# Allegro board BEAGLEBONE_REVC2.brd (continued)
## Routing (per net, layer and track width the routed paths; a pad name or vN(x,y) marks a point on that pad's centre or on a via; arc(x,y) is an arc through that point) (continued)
DDR_CSN: length 26.9
  TOP w0.121: R63.1 62.17,30.8 v1(63.12,31.75) ; v1(74.73,31.49) 74.33,31.89 U6.L8
  LYR3 w0.133: v1(74.73,31.49) 73.53,31.49 73.41,31.62 73.41,31.88 73.28,32 71.37,32 71.25,32.13 71.25,33.4 71.12,33.53 67.94,33.53 67.82,33.4 67.82,32.26 67.69,32.13 65.53,32.13 65.41,32 65.41,29.46 65.28,29.34 64.77,29.34 64.64,29.21 64.64,27.18 64.52,27.05 64.14,27.05 64.01,27.18 64.01,31.62 63.88,31.75 v1(63.12,31.75)
DDR_D0: length 27.2
  TOP w0.121: U6.G8 74.33,35.09 v1(74.73,35.49)
  LYR3 w0.121: 73.66,35.89 74.33,35.89 v1(74.73,35.49)
  LYR3 w0.133: v1(62.23,36.96) 61.72,37.47 61.72,38.48 64.52,41.27 65.02,41.27 65.91,42.16 67.31,42.16 67.94,41.53 70.1,41.53 72.39,39.24 72.39,34.54 72.64,34.29 73.15,34.29 73.4,34.54 73.4,35.63 73.66,35.89
  BOTTOM w0.121: R44.1 60.13,36.51 60.58,36.96 v1(62.23,36.96)
DDR_D1: length 27.1
  TOP w0.121: U6.G2 v1(69.13,35.49)
  BOTTOM w0.121: R45.1 63.75,37.47 63.88,37.59 63.88,37.97 63.75,38.1 63.37,38.1 63.25,38.23 63.25,38.48 63.37,38.61 63.75,38.61 63.88,38.73 63.88,38.99 63.75,39.12 62.36,39.12 62.23,39.24 62.23,39.63 62.36,39.76 62.65,39.76 62.85,39.76 62.85,39.76 63.5,39.76 63.63,39.88 63.63,41.4 63.75,41.53 64.15,41.53 64.27,41.4 64.27,37.21 64.15,37.08 63.75,37.08 63.63,36.96 63.63,36.7 63.75,36.58 64.01,36.58 64.14,36.45 64.14,36.2 64.01,36.07 63.75,36.07 63.63,35.94 63.63,35.69 63.75,35.56 64.14,35.56 65.41,34.29 68.5,34.29 68.73,34.52 68.73,35.09 v1(69.13,35.49)
DDR_D2: length 27
  TOP w0.121: U6.H7 v1(73.93,34.69) ; v1(62.23,40.77) 61.79,40.32 R46.1
  LYR3 w0.121: v1(73.93,34.69) 74.33,35.09 74.9,35.09 75.86,35.09
  LYR3 w0.133: v1(62.23,40.77) 63.63,42.16 63.63,42.8 64.14,43.31 69.47,43.31 69.98,43.81 73.79,43.81 76.2,41.4 76.2,35.43 75.86,35.09
DDR_D3: length 27.1
  TOP w0.121: U6.H3 v1(69.93,34.69) ; v1(66.04,41.27) R47.1
  LYR3 w0.133: v1(66.04,41.27) 66.45,41.68 67.03,41.68 67.69,41.02 69.9,41.02 71.88,39.04 71.88,34.82 71.75,34.69 71.5,34.69 71.37,34.82 71.37,38.86 71.25,38.99 70.99,38.99 70.87,38.86 70.87,34.82 70.74,34.69 v1(69.93,34.69)
DDR_D4: length 27
  TOP w0.121: U6.H1 v1(68.33,34.69)
  BOTTOM w0.121: R48.1 59.94,38.42 60.07,38.54 60.07,38.75 60.18,38.86 60.34,38.86 60.45,38.75 60.45,37.97 60.58,37.85 60.83,37.85 60.96,37.97 60.96,38.73 61.09,38.86 61.21,38.86 61.34,38.73 61.34,37.97 61.47,37.85 62.61,37.85 62.74,37.97 62.74,38.73 62.61,38.86 62.1,38.86 61.98,38.99 61.98,39.88 62.1,40.01 62.99,40.01 63.12,40.13 63.12,42.67 63.25,42.8 63.5,42.8 63.63,42.67 63.63,41.91 63.75,41.78 65.15,41.78 65.28,41.66 65.28,41.27 65.15,41.15 64.65,41.15 64.52,41.02 64.52,35.55 65.39,34.69 v1(68.33,34.69)
DDR_D5: length 27.1
  TOP w0.121: U6.H9 75.53,34.69 v1(75.53,34.69)
  LYR3 w0.133: v1(75.53,34.69) 76.07,34.69 76.33,34.44 76.33,34.04 76.07,33.78 72.52,33.78 72.14,34.16 72.14,39.12 69.98,41.27 67.82,41.27 67.18,41.92 66.05,41.92 65.15,41.02 64.64,41.02 62.23,38.61 v1(62.23,38.35)
  BOTTOM w0.121: R49.1 61.21,39.37 v1(62.23,38.35)
DDR_D6: length 27.2
  TOP w0.121: U6.F1 v1(68.33,36.29)
  BOTTOM w0.121: R50.1 60.58,40.32 60.71,40.45 60.71,40.89 60.83,41.02 61.59,41.02 61.72,40.89 61.72,40.45 61.85,40.32 62.61,40.32 62.74,40.45 62.74,42.16 62.61,42.29 60.2,42.29 60.07,42.42 60.07,42.93 60.2,43.05 63.75,43.05 63.88,42.93 63.88,42.16 64.01,42.04 65.41,42.04 65.53,41.91 65.53,41.02 65.41,40.89 64.9,40.89 64.77,40.77 64.77,39.88 64.9,39.75 65.41,39.75 65.53,39.62 65.53,39.37 65.41,39.24 64.9,39.24 64.77,39.12 64.77,36.58 65.06,36.29 v1(68.33,36.29)
DDR_D7: length 26.9
  TOP w0.121: v1(75.53,36.29) 75.53,36.29 U6.F9
  LYR3 w0.133: v1(62.23,41.78) 61.59,41.15 61.59,40.49 61.85,40.23 62.33,40.23 64.14,42.04 64.64,42.04 65.66,43.05 69.6,43.05 70.1,43.56 73.66,43.56 75.95,41.27 75.95,36.7 v1(75.53,36.29)
  BOTTOM w0.121: v1(62.23,41.78) 60.58,41.78 60.07,41.27 R51.1
DDR_D8: length 27.2
  TOP w0.121: v1(63.12,35.05) 61.72,33.66 R52.1 ; U6.C8 74.33,38.29 v1(74.73,37.89)
  LYR3 w0.121: 73.15,39.24 73.41,39.24 74.73,37.92 v1(74.73,37.89)
  LYR3 w0.133: 73.15,39.24 70.36,42.04 68.2,42.04 67.56,42.67 65.66,42.67 64.77,41.78 64.26,41.78 60.2,37.72 60.2,35.81 61.37,34.65 62.71,34.65 v1(63.12,35.05)
DDR_D9: length 26.9
  TOP w0.121: v1(62.23,35.05) 61.79,34.61 R53.1 ; U6.C2 v1(69.13,38.69)
  LYR3 w0.121: 68.07,38.29 68.73,38.29 v1(69.13,38.69)
  LYR3 w0.133: v1(62.23,35.05) 61.47,35.05 60.58,35.94 60.58,37.59 60.71,37.72 60.96,37.72 61.09,37.59 61.09,36.2 61.62,35.66 62.61,35.66 62.71,35.76 62.71,36.42 62.84,36.55 63.4,36.55 63.75,36.2 64.74,36.2 64.87,36.32 64.87,37.72 65,37.85 65.66,37.85 65.79,37.72 65.79,34.29 65.91,34.16 66.17,34.16 66.29,34.29 66.29,38.73 66.42,38.86 67.69,38.86 67.82,38.73 67.82,38.42 67.94,38.29 68.07,38.29
DDR_D10: length 27.3
  TOP w0.121: U6.D7 72.79,37.49 72.67,37.62 72.67,40.92 72.77,41.02 74.42,41.02 74.55,41.15 74.55,42.42 74.42,42.55 v1(72.9,42.55) ; v1(71.75,42.55) 71.75,40.89 71.63,40.77 68.04,40.77 67.69,40.42 67.69,36.2 67.4,35.91 63.75,35.91 63.41,35.56 R54.1
  LYR3 w0.133: v1(72.9,42.55) v1(71.75,42.55)
DDR_D11: length 26.9
  TOP w0.121: U6.D3 v1(69.93,37.89)
  LYR3 w0.121: v1(69.93,37.89) 69.53,37.49 67.94,37.49
  LYR3 w0.133: v1(64.01,35.05) 63.75,35.05 62.99,34.29 60.07,34.29 59.94,34.16 59.94,33.66 60.07,33.53 63.47,33.53 63.6,33.66 63.6,34.04 63.73,34.16 64.29,34.16 64.41,34.04 64.41,33.63 64.52,33.53 65.66,33.53 65.79,33.4 65.79,33.02 65.91,32.89 66.93,32.89 67.06,33.02 67.06,34.29 67.18,34.42 67.69,34.42 67.82,34.54 67.82,37.36 67.94,37.49
  BOTTOM w0.121: R55.1 60.13,32.7 62.08,34.65 63.61,34.65 v1(64.01,35.05)
DDR_D12: length 27.3
  TOP w0.121: U6.D1 v1(68.33,37.89)
  LYR3 w0.133: v1(68.33,37.89) 67.69,37.89 67.56,37.76 67.56,34.92 67.44,34.8 67.18,34.8 67.06,34.92 67.06,38.35 66.93,38.48 66.67,38.48 66.55,38.35 66.55,33.27 66.42,33.15 66.17,33.15 66.04,33.27 66.04,33.66 65.91,33.78 64.77,33.78 64.65,33.9 64.65,35.43 64.52,35.56 63.25,35.56 63.12,35.69 v1(63.12,36.07)
  BOTTOM w0.121: v1(63.12,36.07) 63.12,35.69 62.99,35.56 61.85,35.56 61.72,35.43 61.72,34.65 61.62,34.54 61.44,34.54 61.34,34.65 61.34,34.92 61.24,35.03 61.07,35.03 60.96,34.92 60.96,33.88 60.86,33.78 60.68,33.78 60.58,33.88 60.58,34.19 60.48,34.29 60.3,34.29 60.2,34.19 60.2,33.76 60.1,33.66 R56.1
DDR_D13: length 27
  TOP w0.121: v1(74.73,37.09) U6.D9
  LYR3 w0.133: v1(74.73,37.09) 74.22,36.58 73.41,36.58 73.15,36.32 73.15,35.94 73.03,35.81 72.77,35.81 72.64,35.94 72.64,39.37 70.23,41.78 68.07,41.78 67.44,42.42 65.79,42.42 64.9,41.53 64.39,41.53 61.47,38.61 61.47,36.83 v1(62.23,36.07)
  BOTTOM w0.121: v1(62.23,36.07) 61.59,36.07 60.13,34.61 R57.1
DDR_D14: length 26.8
  TOP w0.121: U6.B1 v1(68.33,39.49)
  LYR3 w0.133: v1(68.33,39.49) 67.96,39.12 65.28,39.12 65.15,39.24 65.15,39.75 65.28,39.88 65.79,39.88 66.04,40.13 66.42,40.13 66.67,39.88 67.69,39.88 67.82,40.01 67.82,40.26 67.69,40.39 67.18,40.39 66.8,40.77 64.9,40.77 64.77,40.64 64.77,38.35 64.64,38.23 64.39,38.23 64.26,38.35 64.26,39.62 64.14,39.75 63.88,39.75 63.75,39.62 63.75,37.59 63.63,37.47 63.37,37.47 63.25,37.59 63.25,38.61 63.12,38.73 62.87,38.73 62.74,38.61 62.74,37.97 62.61,37.85 62.36,37.85 62.23,37.72 62.23,37.49 62.36,37.36 62.71,37.36 v1(63.12,36.96)
  BOTTOM w0.121: R58.1 60.07,35.56 60.98,36.47 62.63,36.47 v1(63.12,36.96)
DDR_D15: length 26.9
  TOP w0.121: U6.B9 74.73,39.49 74.73,40.22 v1(74.73,40.29) ; R59.1 61.66,38.42 62.01,38.77 63.88,38.77 64.01,38.64 64.01,38 64.14,37.87 64.64,37.87 64.77,38 64.77,38.99 64.9,39.12 66.17,39.12 66.29,38.99 66.29,36.83 66.42,36.7 66.8,36.7 66.93,36.83 66.93,40.77 67.69,41.53 68.45,41.53 v1(69.47,42.55)
  LYR3 w0.133: v1(74.73,40.29) 74.73,41.83 74.42,42.14 73.79,42.14 73.64,42.29 73.64,43.07 73.41,43.31 70.23,43.31 v1(69.47,42.55)
DDR_DQM0: length 27.1
  TOP w0.121: v1(66.8,41.27) 66.67,41.15 66.67,40.26 66.55,40.13 66.29,40.13 66.17,40.26 66.17,40.64 66.04,40.77 65.82,40.77 65.69,40.64 65.69,39.62 65.57,39.5 64.9,39.5 64.77,39.62 64.77,40.77 64.64,40.89 64.39,40.89 64.26,40.77 64.26,39.24 64.14,39.12 63.88,39.12 63.75,39.24 63.75,40.77 63.63,40.89 63.37,40.89 63.25,40.77 63.25,39.24 63.12,39.12 62.87,39.12 62.74,39.24 62.74,40.13 62.61,40.26 62.36,40.26 62.23,40.13 62.23,39.24 62.1,39.12 61.85,39.12 61.59,39.37 R67.1 ; U6.F3 v1(69.93,36.29)
  LYR3 w0.121: 69.53,40.58 69.53,39.22 69.63,39.12 69.88,39.12 69.98,39.22 69.98,39.78 70.08,39.88 70.38,39.88 70.48,39.78 70.48,36.42 70.36,36.29 v1(69.93,36.29)
  LYR3 w0.133: v1(66.8,41.27) 67.31,40.77 69.34,40.77 69.53,40.58
DDR_DQM1: length 26.9
  TOP w0.121: R70.1 61.72,32.7 63.18,34.16 68.2,34.16 68.47,33.89 70.61,33.89 70.74,34.02 70.74,35.05 70.87,35.18 71.12,35.18 71.25,35.05 71.25,33.66 71.37,33.53 71.63,33.53 71.75,33.66 71.75,38.86 71.63,38.99 71.37,38.99 71.25,38.86 71.25,35.81 71.12,35.69 70.87,35.69 70.74,35.81 70.74,38.68 U6.B3
DDR_DQS0: length 27
  TOP w0.121: R68.1 63.31,42.23 64.9,43.81 74.17,43.81 74.3,43.69 74.3,43.43 74.17,43.31 72.3,43.31 72.17,43.18 72.17,34.92 72.3,34.8 72.77,34.8 72.9,34.92 72.9,35.76 73.03,35.89 U6.F7
DDR_DQS1: length 27.2
  TOP w0.121: v1(70.99,42.55) 71.37,42.16 71.37,41.15 71.25,41.02 67.94,41.02 67.44,40.51 67.44,36.32 67.31,36.2 64.9,36.2 64.77,36.32 64.77,37.25 64.64,37.37 64.39,37.37 64.26,37.25 64.26,36.32 64.14,36.2 63.75,36.2 63.63,36.32 63.63,37.25 63.5,37.37 62.77,37.37 62.65,37.25 62.65,36.64 62.52,36.51 R71.1
  TOP w0.305: U6.B7 73.04,39.58 73.04,40.2 v1(73.13,40.29)
  LYR3 w0.133: v1(73.13,40.29) 72.77,40.29 72.64,40.42 72.64,41.94 72.54,42.04 72.24,42.04 72.14,41.94 72.14,41.27 72.01,41.15 71.88,41.15 71.75,41.27 71.75,41.78 71.63,41.91 71.12,41.91 70.99,42.04 v1(70.99,42.55)
DDR_DQSN0: length 27.2
  TOP w0.121: U6.E8 73.93,36.29 72.52,36.29 72.42,36.4 72.42,41.27 72.55,41.4 73.28,41.4 73.41,41.53 73.41,41.91 73.28,42.04 72.55,42.04 72.42,42.16 72.42,42.95 72.52,43.05 74.42,43.05 74.55,43.18 74.55,43.94 74.42,44.07 64.64,44.07 63.75,43.18 R69.1
DDR_DQSN1: length 27
  TOP w0.121: v1(70.23,42.55) 70.23,41.4 70.1,41.27 69.98,41.27 69.85,41.4 69.85,41.91 69.72,42.04 69.6,42.04 69.47,41.91 69.47,41.4 69.34,41.27 67.82,41.27 67.18,40.64 67.18,36.58 67.06,36.45 66.17,36.45 66.04,36.58 66.04,37.72 65.91,37.85 65.25,37.85 65.02,37.62 61.88,37.62 61.72,37.47 R72.1
  TOP w0.305: U6.A8 v1(73.93,40.29)
  LYR3 w0.133: v1(73.93,40.29) 74.17,40.52 74.17,40.77 74.04,40.89 73.15,40.89 73.03,41.02 73.03,41.27 73.15,41.4 74.17,41.4 74.3,41.53 74.3,41.78 74.17,41.91 73.53,41.91 73.41,42.04 73.41,42.8 73.15,43.05 70.36,43.05 70.23,42.93 v1(70.23,42.55)
DDR_ODT: length 27.2
  TOP w0.121: v1(62.23,29.84) R73.1 ; U6.K9 v1(75.53,32.29)
  LYR3 w0.121: 73.66,32.69 74.12,32.69 74.33,32.47 74.33,32.12 74.57,31.89 75.13,31.89 v1(75.53,32.29)
  LYR3 w0.133: v1(62.23,29.84) 61.72,29.84 61.59,29.72 61.59,28.96 61.47,28.83 60.45,28.83 60.33,28.96 60.33,33.02 60.45,33.15 64.39,33.15 64.52,33.02 64.52,32.77 64.64,32.64 67.18,32.64 67.31,32.77 67.31,33.91 67.44,34.04 71.5,34.04 71.75,33.78 71.75,32.89 71.96,32.69 73.66,32.69
DDR_RASN: length 27.3
  TOP w0.121: U6.K7 73.93,32.29 v1(73.93,32.29)
  LYR3 w0.133: v1(63.12,29.84) 63.12,30.23 62.87,30.48 61.72,30.48 61.59,30.61 61.59,32.13 61.72,32.26 64.26,32.26 64.39,32.13 64.39,30.23 64.52,30.1 64.77,30.1 64.9,30.23 64.9,32.26 65.02,32.38 67.44,32.38 67.56,32.51 67.56,33.66 67.69,33.78 71.37,33.78 71.5,33.66 71.5,32.42 71.63,32.29 v1(73.93,32.29)
  BOTTOM w0.121: R65.1 60.2,29.84 60.71,29.34 62.61,29.34 v1(63.12,29.84)
DDR_RESETN: length 3.5
  TOP w0.121: TP3.1 58.23,30.8 57.14,31.89 55.93,31.89 U5.G2
DDR_VREF: length 21
  TOP w0.121: v1(54.33,33.49) U5.J4 ; U6.J2 v1(69.13,33.09)
  BOTTOM w0.121: v1(54.33,33.49) 54.73,33.09 55.44,33.09 55.63,33.27 57.02,33.27 58.04,32.26 60.33,32.26 60.77,32.7 R74.2 R75.1 62.04,34.04 62.17,34.16 64.77,34.16 65.15,33.78 68.44,33.78 v1(69.13,33.09) 67.93,31.89 C118.1
DDR_VTP: length 18.8
  TOP w0.305: v1(55.13,33.49) U5.J3
  LYR4 w0.381: v1(64.77,20.32) 59.05,26.04 59.05,30.1 55.66,33.49 v1(55.13,33.49)
  BOTTOM w0.381: R76.2 v1(64.77,20.32)
DDR_WEN: length 26.9
  TOP w0.121: R66.1 56.83,22.16 57.15,21.84 61.59,21.84 63.79,24.04 66.26,24.04 67.09,23.21 67.78,23.21 v1(68.2,23.62) ; U6.K3 v1(69.93,32.29)
  LYR3 w0.133: v1(69.93,32.29) 70.47,31.75 72.01,31.75 72.77,30.99 72.77,29.08 71.63,27.94 71.25,27.94 69.85,26.54 69.85,25.78 68.83,24.77 68.83,24.26 v1(68.2,23.62)
EHRPWM1A: length 55.8
  TOP w0.121: v1(36.83,44.2) 39.5,44.2 40.64,43.05 40.89,43.05 41.66,42.29 44.58,42.29 45.53,41.34 45.53,40.69 U5.U14
  LYR4 w0.133: v1(36.83,44.2) 36.83,42.04 36.32,41.53 36.32,39.12 36.83,38.61 37.34,38.61 38.61,37.34 38.61,35.56 35.69,32.64 35.69,26.29 36.07,25.91 36.07,21.21 35.43,20.57 35.43,15.88 35.94,15.37 36.45,15.37 37.06,14.76 37.06,6.83 34.92,4.7 P9.14
EHRPWM1B: length 45.2
  TOP w0.121: v1(45.53,39.89) U5.T14
  LYR4 w0.133: P9.16 37.47,5.59 38.54,6.67 38.54,14.67 37.69,15.52 37.69,26.34 37.4,26.63 36.87,26.63 36.7,26.8 36.7,28.83 39.5,31.62 39.5,38.48 39.24,38.73 39.24,39.37 40.26,40.39 45.03,40.39 v1(45.53,39.89)
EHRPWM2A: length 29.6
  TOP w0.121: U5.U10 49.53,40.69 49.53,41.61 49.38,41.77 49.38,41.89 46.62,44.65 46.62,47.9 46.51,48.01 46.33,48.01 46.23,47.9 46.23,44.81 46.13,44.7 45.95,44.7 45.85,44.81 45.85,47.9 45.75,48.01 45.57,48.01 45.47,47.9 45.47,44.81 45.36,44.7 45.19,44.7 45.09,44.81 45.09,48.32 44.83,48.58 44.13,48.58 43.69,49.02 43.69,51.05 43.43,51.31 42.8,51.31 42.55,51.05 P8.19
EHRPWM2B: length 28.6
  TOP w0.121: v1(48.73,39.89) U5.T10
  LYR4 w0.133: v1(48.73,39.89) 48.15,40.47 47.8,40.47 44.32,43.94 40.39,43.94 40.13,44.2 40.13,48.01 39.88,48.26 39.5,48.26 39.24,48.01 39.24,47.37 38.99,47.12 38.61,47.12 38.35,47.37 38.35,48.01 38.1,48.26 37.72,48.26 37.47,48.01 37.47,45.47 37.21,45.21 36.45,45.21 36.2,45.47 36.2,48.9 P8.13
EMU2R: length 2.8
  BOTTOM w0.121: R183.2 P7.17
EMU3R: length 4.9
  BOTTOM w0.121: P7.18 68.07,17.14 67.82,17.4 R184.1
EMU4R: length 2.8
  BOTTOM w0.121: R185.2 P7.19
EMU_RSTN: length 4.9
  BOTTOM w0.121: C156.1 60.45,15.11 60.58,15.24 61.21,15.24 61.47,15.49 R182.2 P7.15
ENZ_KALDO_1P8V: length 5.2
  TOP w0.121: U5.B4 53.94,28.29 54.33,27.9 54.33,25.7 54.07,25.44 54.07,24.73 54.1,24.7 54.1,24.64 54.93,23.81 R79.2
F_ADBUS0: length 2.6
  TOP w0.121: U12.16 48.84,6.62 48.56,6.35 v1(48.26,6.35)
  BOTTOM w0.121: v1(48.26,6.35) R164.1
F_ADBUS1: length 5.4
  TOP w0.121: v1(52.7,6.99) 51.82,7.87 51.82,9.4 51.63,9.58 U12.17
  BOTTOM w0.121: v1(52.7,6.99) R165.1
F_ADBUS2: length 4.7
  TOP w0.121: v1(52.7,8.26) 52.07,8.89 52.07,9.78 51.76,10.09 U12.18
  BOTTOM w0.121: R166.1 v1(52.7,8.26)
F_ADBUS3: length 3.9
  TOP w0.121: v1(52.7,9.53) 51.65,10.58 U12.19
  BOTTOM w0.121: v1(52.7,9.53) R168.1
F_ADBUS4: length 3.7
  TOP w0.121: v1(52.7,10.79) 51.92,11.58 U12.21
  BOTTOM w0.121: v1(52.7,10.79) R169.1
F_ADBUS6: length 3.6
  TOP w0.121: U12.23 52.19,12.58 v1(52.7,12.06)
  BOTTOM w0.121: v1(52.7,12.06) R170.1
F_ADBUS7: length 5.9
  TOP w0.121: v1(52.7,13.34) 52.7,13.72 52.83,13.84 52.83,15.24 51.99,16.09 U12.30
  BOTTOM w0.121: v1(52.7,13.34) R171.1
F_EECS: length 5.1
  TOP w0.121: R173.2 v1(36.51,9.84) 36.76,10.09 U12.63
  BOTTOM w0.121: v1(36.51,9.84) U13.5
F_EEDATA: length 7.9
  TOP w0.121: R188.2 36.19,11.75 v1(36.2,11.74) 36.85,11.09 U12.61
  BOTTOM w0.121: v1(36.2,11.74) 36.2,11.74 34.85,11.74 33.91,10.79 U13.3
F_EEDOUT: length 11.7
  TOP w0.121: R187.2 33.9,8.89 33.66,8.64 33.66,7.37 v1(33.15,6.86) ; R188.1 v1(33.66,11.75)
  LYR4 w0.133: v1(33.66,11.75) 32.64,10.73 32.64,7.37 v1(33.15,6.86)
  BOTTOM w0.121: v1(33.15,6.86) 33.66,7.37 33.66,8.38 33.15,8.89 U13.1
F_EESK: length 5.1
  TOP w0.121: R174.2 v1(36.51,10.79) 36.72,10.58 U12.62
  BOTTOM w0.121: v1(36.51,10.79) U13.4
FT_DM: length 53.6
  TOP w0.114: U11.28 18.55,39.4 18.26,39.1 18.26,38.24 20.18,36.32 22.49,36.32 23.99,37.82 32.54,37.82 34.29,36.07 34.29,35.42 35.28,34.43 35.28,30.11 35.81,29.58 35.81,22.59 36.97,21.44 38.89,21.44 39.81,20.51 39.81,18.59 42.14,16.27 42.14,15.51 44.56,13.09 44.56,8.94 44.33,8.72
  TOP w0.121: 44.33,8.72 U12.7
FT_DP: length 53.7
  TOP w0.114: 44.84,8.72 44.84,13.2 42.42,15.62 42.42,16.38 40.09,18.71 40.09,20.63 39,21.72 37.08,21.72 36.09,22.71 36.09,29.69 35.56,30.23 35.56,34.54 34.57,35.53 34.57,36.18 32.65,38.1 23.88,38.1 22.38,36.6 20.29,36.6 18.54,38.35 18.54,38.99 18.67,39.12 18.89,39.12 19.14,38.87 U11.1
  TOP w0.121: 44.84,8.72 U12.8
FT_REF: length 2.3
  TOP w0.121: U12.6 43.84,6.65 v1(44.13,6.35)
  BOTTOM w0.121: R167.2 v1(44.13,6.35)
FT_RESETN: length 2.8
  TOP w0.121: U12.14 v1(47.84,9.53)
  BOTTOM w0.121: v1(47.84,9.53) 48.04,9.53 48.26,9.75 48.26,10.29
FT_SRESET: length 37.8
  TOP w0.121: U12.26 v1(52.32,14.09) ; v1(33.97,24.77) 33.97,25.29 U14.5
  LYR3 w0.133: v1(52.32,14.09) 48.38,14.09 47.62,13.34 42.93,13.34 42.16,14.1 40.26,14.1 38.61,12.45 33.72,12.45 v1(33.02,11.75)
  LYR4 w0.133: v1(33.02,11.75) 33.02,12.05 33.03,12.06 33.03,16.9 33.53,17.4 33.53,24.32 v1(33.97,24.77)
  BOTTOM w0.121: v1(33.97,24.77) R162.2
FT_SRESETB: length 1.9
  TOP w0.121: U16.6 34.12,42.97 33.91,43.18 v1(33.53,43.18)
  BOTTOM w0.121: v1(33.53,43.18) R163.1
FT_SRESETN: length 29.8
  TOP w0.121: v1(38.73,20.32) 37.97,21.08 36.7,21.08 35.43,22.35 35.43,24 35.18,24.26 33.53,24.26 33.02,24.77 33.02,25.27 32.51,25.79 U14.3
  LYR3 w0.133: v1(53.21,17.14) 52.7,17.14 50.16,19.68 44.58,19.68 43.43,20.83 40.26,20.83 39.75,20.32 v1(38.73,20.32)
  BOTTOM w0.121: v1(53.21,17.14) 54.1,16.26 R172.1
FT_VBUS: length 48.2
  TOP w0.121: v1(30.86,40.01) 28.45,40.01 27.69,39.24 23.24,39.24 22.87,38.87 U11.7 ; v1(32.38,11.75) 32.83,12.19 33.78,12.19 33.91,12.32 36.83,12.32 R181.2 37.06,12.09 U12.59 ; U14.6 33.24,25.79 v1(33.02,26.01)
  LYR4 w0.133: v1(32.38,11.75) 32.79,12.15 32.79,16.1 32.51,16.38 32.51,25.5 v1(33.02,26.01) 32.99,26.04 31.75,26.04 30.86,26.92 v1(30.86,40.01)
GPIO0_7: length 42.6
  TOP w0.121: v1(45.97,20.32) 45.11,21.18 44.48,21.18 43.69,21.97 R202.1 43.31,22.61 43.18,22.73 43.18,23.5 43.05,23.62 R217.1
  BOTTOM w0.121: P9.42 69.34,5.59 52.45,5.59 51.31,6.73 51.31,11.68 50.8,12.19 48.77,12.19 47.18,13.78 47.18,16.57 45.97,17.78 v1(45.97,20.32)
GPIO0_7SRC: length 13.2
  TOP w0.121: R217.2 42.67,21.84 42.06,21.23 41,21.23 40.13,22.1 40.13,24.38 39.88,24.64 39.88,27.94 40.29,28.36 41.31,28.36 42.04,29.09 U5.C18
GPIO0_26: length 29.2
  TOP w0.121: v1(47.93,39.89) U5.T11
  LYR3 w0.133: v1(47.93,39.89) 43.75,44.07 39.5,44.07 39.24,44.32 39.24,44.83 39.5,45.09 42.49,45.09 42.67,45.27 42.67,45.53 42.49,45.72 v1(36.83,45.72)
  LYR4 w0.133: v1(36.83,45.72) 36.83,49.02 36.07,49.78 36.07,51.56 P8.14
GPIO0_27: length 29.5
  TOP w0.121: P8.17 38.61,48.77 37.72,48.77 37.59,48.64 37.59,45.34 37.72,45.21 37.97,45.21 38.1,45.34 38.1,47.88 38.23,48.01 38.48,48.01 38.61,47.88 38.61,45.34 38.73,45.21 38.99,45.21 39.12,45.34 39.12,47.88 39.24,48.01 39.5,48.01 39.62,47.88 39.62,45.18 40.99,43.81 42.55,43.81 42.8,43.56 44.96,43.56 47.13,41.39 47.13,40.69 U5.U12
GPIO1_0: length 11.7
  TOP w0.121: U5.U7 51.93,40.69 51.93,41.44 49.05,44.32 49.05,49.05 P8.25
GPIO1_1: length 14.1
  TOP w0.121: U5.V7 51.53,41.49 47.88,45.14 47.88,48.51 48.9,49.53 48.9,51.44 P8.24
GPIO1_2: length 32
  TOP w0.121: v1(51.13,39.09) U5.R8
  LYR3 w0.121: v1(51.13,39.09) 50.73,39.49 50.73,40.33
  LYR3 w0.133: 50.73,40.33 44.32,46.74 31.75,46.74 30.23,48.26 26.67,48.26 P8.5
GPIO1_3: length 33.5
  TOP w0.121: v1(51.13,39.89) U5.T8
  LYR3 w0.133: P8.6 26.04,51.44 26.04,49.78 27.3,48.51 30.48,48.51 32,46.99 44.45,46.99 51.13,40.31 v1(51.13,39.89)
GPIO1_4: length 11.5
  TOP w0.121: U5.U8 51.13,40.69 51.13,41.54 47.62,45.05 P8.23
GPIO1_5: length 14
  TOP w0.121: P8.22 46.35,51.44 46.35,49.53 47.37,48.51 47.37,44.95 50.27,42.05 50.73,41.59 U5.V8
GPIO1_6: length 33.8
  TOP w0.121: v1(50.33,39.09) U5.R9
  LYR3 w0.133: P8.3 26.16,46.23 42.67,46.23 46.61,42.29 48.01,42.29 49.91,40.39 49.91,39.51 v1(50.33,39.09)
GPIO1_7: length 35.4
  TOP w0.121: v1(50.33,39.89) U5.T9
  LYR3 w0.133: v1(50.33,39.89) 50.33,40.35 44.2,46.48 26.42,46.48 23.5,49.4 23.5,51.44 P8.4
GPIO1_12: length 28.9
  TOP w0.121: v1(47.13,39.89) U5.T12
  LYR4 w0.133: v1(47.13,39.89) 47.13,40.25 43.94,43.43 39.11,43.43 38.86,43.68 38.86,46.23 38.61,46.48 38.23,46.48 37.97,46.23 37.97,44.96 37.72,44.7 34.67,44.7 31.11,48.26 31.11,51.44 P8.12
GPIO1_13: length 28.8
  TOP w0.121: v1(47.13,39.09) U5.R12
  LYR3 w0.121: 46.73,40.27 46.73,39.49 v1(47.13,39.09)
  LYR3 w0.133: 46.73,40.27 44.83,42.16 41.66,42.16 40.89,41.4 40.13,41.4 39.37,42.16 37.14,42.16 36.96,42.35 36.96,42.61 37.14,42.8 39.62,42.8 39.88,43.05 39.88,43.31 39.62,43.56 36.07,43.56 35.69,43.94 v1(35.69,45.72)
  LYR4 w0.133: P8.11 35.69,46.86 v1(35.69,45.72)
GPIO1_14: length 29.5
  TOP w0.121: U5.V13 46.73,41.41 44.83,43.31 42.67,43.31 42.42,43.56 40.89,43.56 39.6,44.86 37.37,44.86 37.25,44.99 37.25,48.54 37.14,48.64 36.8,48.64 36.7,48.54 36.7,47.35 36.6,47.24 36.42,47.24 36.32,47.35 36.32,48.54 36.22,48.64 36.04,48.64 35.94,48.54 35.94,47.35 35.84,47.24 35.53,47.24 35.43,47.35 35.43,49.05 35.53,49.15 38.35,49.15 38.73,49.53 38.73,51.44 P8.16
GPIO1_15: length 29.6
  TOP w0.121: P8.15 36.07,51.56 31.5,51.56 31.24,51.31 31.24,48.76 31.5,48.51 33.79,48.51 36.1,46.19 36.1,44.9 36.39,44.61 39.43,44.61 40.74,43.31 42.29,43.31 42.55,43.05 44.7,43.05 46.33,41.43 46.33,40.69 U5.U13
GPIO1_16: length 50.4
  TOP w0.121: v1(46.33,39.09) U5.R13
  LYR4 w0.121: v1(46.33,39.09) 46.33,39.27 45.93,39.67 45.93,40.09
  LYR4 w0.133: 45.93,40.09 45.93,40.18 45.47,40.64 40.01,40.64 38.86,39.5 38.86,38.61 39.12,38.35 39.12,33.78 38.54,33.21 38.54,31.18 36.45,29.08 36.45,26.54 36.7,26.29 36.7,16 38.23,14.48 38.23,6.99 36.32,5.08 36.32,3.05 P9.15
GPIO1_17: length 58.2
  TOP w0.121: U5.V14 45.93,41.45 44.58,42.8 v1(41.91,42.8)
  LYR4 w0.121: 43.43,39.49 45.73,39.49 45.93,39.29 45.93,38.93 46.16,38.69 46.5,38.69 46.73,38.92 46.73,39.61 46.73,40.14 46.48,40.39
  LYR4 w0.133: v1(41.91,42.8) 44.07,42.8 46.48,40.39 ; P9.23 46.23,3.3 46.23,5.08 45.47,5.84 45.47,7.49 44.58,8.38 44.58,18.41 43.94,19.05 43.94,20.32 42.67,21.59 42.67,21.95 42.37,22.25 41.12,22.25 40.89,22.48 40.89,23.24 41.78,24.13 41.78,27.56 41.91,27.69 41.91,37.08 42.67,37.85 42.67,38.73 43.43,39.49
GPIO1_28: length 50.9
  TOP w0.121: U5.U18 42.58,40.14 40.24,40.14 40.01,39.91 36.17,39.91 35.31,40.77 32.51,40.77 v1(31.75,40.01)
  LYR4 w0.133: P9.12 33.66,5.71 33.66,10.79 34.42,11.56 34.42,20.7 34.04,21.08 34.04,23.11 34.42,23.5 34.42,25.65 33.53,26.54 32.13,26.54 31.24,27.43 31.24,39.5 v1(31.75,40.01)
GPIO1_29: length 13.7
  TOP w0.121: U5.V6 52.33,41.39 50.01,43.72 50.01,48.1 51.44,49.53 51.44,51.44 P8.26
GPIO1_30: length 12.2
  TOP w0.121: U5.U9 50.33,40.69 50.33,41.64 50.03,41.94 50.03,41.95 47.12,44.85 47.12,48.13 P8.21
GPIO1_31: length 15.6
  TOP w0.121: U5.V9 49.93,41.69 49.78,41.84 46.86,44.76 46.86,48.01 45.85,49.02 44.32,49.02 44.07,49.28 44.07,51.18 P8.20
GPIO2_1: length 17.9
  TOP w0.121: U5.V12 47.53,41.37 45.09,43.81 42.93,43.81 42.67,44.07 41.15,44.07 40.01,45.21 40.01,48.39 41.27,49.66 41.27,51.44 P8.18
GPIO2_6: length 29.2
  TOP w0.121: U5.R1 56.79,38.69 58.1,40.01 58.1,42.35 60.07,44.32 63.06,44.32 v1(63.82,45.09) 63.82,45.85
  LYR4 w0.133: v1(63.82,45.09) 63.82,44.13 64.14,43.81 67.82,43.81 72.26,48.26 74.8,48.26 75.56,49.02 P8.45
  BOTTOM w0.121: 63.82,45.85 v1(63.82,45.09)
GPIO2_7: length 29.8
  TOP w0.121: 62.87,45.85 v1(62.87,45.09) 62.36,44.58 59.94,44.58 57.78,42.42 57.78,40.17 56.7,39.09 55.92,39.09 55.53,38.7 U5.R2
  LYR4 w0.133: v1(62.87,45.09) 63.37,45.59 69.22,45.59 72.52,48.9 73.66,48.9 74.3,49.53 74.3,51.44 P8.46
  BOTTOM w0.121: 62.87,45.85 v1(62.87,45.09)
GPIO2_8: length 28.7
  TOP w0.121: v1(55.13,39.09) U5.R3 ; v1(61.91,45.09) 61.91,45.85
  LYR4 w0.133: v1(61.91,45.09) 62.67,45.85 69.09,45.85 71.88,48.64 71.88,50.8 72.39,51.31 72.77,51.31 73.03,51.05 P8.43
  BOTTOM w0.121: v1(55.13,39.09) 55.35,39.09 55.78,39.52 55.78,41.94 57.4,43.56 60.39,43.56 v1(61.91,45.09) 61.91,45.85
GPIO2_9: length 29.1
  TOP w0.121: v1(60.96,45.09) 60.96,45.85 ; v1(54.33,39.09) U5.R4
  LYR4 w0.133: v1(60.96,45.09) 61.98,46.1 68.64,46.1 71.5,48.96 71.5,51.18 P8.44
  BOTTOM w0.121: 60.96,45.85 v1(60.96,45.09) 59.69,43.81 57.28,43.81 55.53,42.07 55.53,39.73 55.3,39.49 54.73,39.49 v1(54.33,39.09)
GPIO2_10: length 29.4
  TOP w0.121: 60.01,45.85 v1(60.01,45.09) 57.47,42.55 57.47,40.29 56.67,39.49 U5.T1
  LYR3 w0.133: P8.41 71.25,49.4 71.25,49.02 71.12,48.9 70.71,48.9 70.61,48.79 70.61,48.62 70.71,48.51 71.14,48.51 71.25,48.4 71.25,48.24 71.14,48.13 70.71,48.13 70.61,48.03 70.61,47.22 70.51,47.12 69.34,47.12 69.22,46.99 69.22,46.74 69.34,46.61 70.48,46.61 70.61,46.48 70.61,46.23 70.48,46.1 69.09,46.1 68.96,45.97 68.96,44.7 68.83,44.58 60.52,44.58 v1(60.01,45.09)
  BOTTOM w0.121: 60.01,45.85 v1(60.01,45.09)
GPIO2_11: length 29.3
  TOP w0.121: U5.T2 55.93,39.89 56.53,39.89 57.15,40.51 57.15,43.18 v1(59.05,45.09) 59.05,45.85
  LYR3 w0.133: P8.42 71.63,51.56 71.63,46.74 69.22,44.32 59.82,44.32 v1(59.05,45.09)
  BOTTOM w0.121: 59.05,45.85 v1(59.05,45.09)
GPIO2_12: length 29.5
  TOP w0.121: 58.1,45.85 v1(58.1,45.09) ; v1(55.13,39.89) U5.T3
  LYR3 w0.133: P8.39 69.09,49.02 69.98,49.02 70.1,48.9 70.1,48.64 69.98,48.51 69.22,48.51 69.09,48.39 69.09,48.23 69.19,48.13 70,48.13 70.1,48.03 70.1,47.73 70,47.62 68.81,47.62 68.71,47.52 68.71,44.96 68.58,44.83 65.66,44.83 64.77,45.72 58.74,45.72 v1(58.1,45.09)
  BOTTOM w0.121: v1(55.13,39.89) 55.13,40.31 55.13,42.05 58.1,45.02 v1(58.1,45.09) 58.1,45.85
GPIO2_13: length 29.8
  TOP w0.121: v1(54.33,39.89) U5.T4 ; 57.15,45.85 v1(57.15,45.09)
  LYR3 w0.133: v1(57.15,45.09) 58.04,45.97 64.9,45.97 65.79,45.09 68.2,45.09 68.45,45.34 68.45,48.77 68.2,49.02 67.06,49.02 66.8,49.28 66.8,51.56 P8.40
  BOTTOM w0.121: v1(54.33,39.89) 54.86,40.42 54.86,42.8 v1(57.15,45.09) 57.15,45.85
GPIO2_22: length 29.6
  TOP w0.121: v1(52.39,44.01) 52.31,43.93 52.31,42.94 53.53,41.72 53.53,40.69 U5.U5
  LYR4 w0.133: P8.27 52.83,50.04 52.83,45.97 52.96,45.85 53.72,45.85 53.85,45.72 53.85,41.78 53.98,41.66 54.61,41.66 54.74,41.78 54.74,44.45 54.86,44.58 55.12,44.58 55.24,44.45 55.24,41.27 55.12,41.15 53.47,41.15 53.34,41.27 53.34,42.29 53.21,42.42 52.83,42.42 52.7,42.29 52.7,41.27 52.58,41.15 52.2,41.15 52.07,41.27 52.07,43.69 v1(52.39,44.01)
GPIO2_23: length 29.6
  TOP w0.121: v1(53.53,39.09) U5.R5
  LYR4 w0.121: v1(53.53,39.09) 53.93,39.49 53.93,40.21
  LYR4 w0.133: 53.93,40.21 54.1,40.39 57.4,40.39 57.53,40.51 57.53,44.07 57.66,44.2 57.91,44.2 58.04,44.07 58.04,40.51 58.17,40.39 58.42,40.39 58.55,40.51 58.55,48.64 58.42,48.77 57.78,48.77 57.66,48.64 57.66,46.99 57.53,46.86 56.77,46.86 56.64,46.99 56.64,48.77 55.24,50.16
GPIO2_24: length 29.4
  TOP w0.121: U5.V5 53.13,41.61 51.94,42.8 51.94,43.51 v1(51.45,44.01)
  LYR4 w0.133: P8.28 51.31,51.31 49.66,51.31 49.02,50.67 49.02,41.27 49.15,41.15 49.4,41.15 49.53,41.27 49.53,44.32 49.66,44.45 49.91,44.45 50.04,44.32 50.04,41.27 50.16,41.15 51.56,41.15 51.69,41.27 51.69,43.77 v1(51.45,44.01)
GPIO2_25: length 28.9
  TOP w0.121: v1(52.73,39.09) U5.R6
  LYR4 w0.121: v1(52.73,39.09) 53.13,39.49 53.13,40.26
  LYR4 w0.133: 53.13,40.26 53.64,40.77 57.02,40.77 57.15,40.89 57.15,44.07 57.02,44.2 56.77,44.2 56.64,44.07 56.64,42.42 56.52,42.29 55.78,42.29 55.65,42.42 55.65,48.64 55.52,48.77 54.86,48.77 54.74,48.64 54.74,46.99 54.61,46.86 53.98,46.86 53.85,46.99 53.85,51.31 55.24,52.7
GPIO3_18: length 11.2
  TOP w0.121: R202.2 44.17,23.14 44.17,21.87 44.61,21.43 45,21.43 45.25,21.67 45.25,25.94 45.9,26.6 46.43,26.6 47.13,27.3 47.13,27.89 U5.B12
GPIO3_19: length 31.2
  TOP w0.121: v1(46.33,28.69) U5.C13
  LYR4 w0.133: v1(46.33,28.69) 45.85,28.21 45.85,26.8 45.47,26.42 45.47,23.37 45.72,23.11 45.72,21.97 48.36,19.33 48.36,7.77 50.16,5.97 50.93,5.97 51.56,5.33 51.56,3.05 P9.27
GPIO3_20: length 5.9
  TOP w0.121: v1(46.33,30.29) U5.D13
  BOTTOM w0.121: v1(46.33,30.29) 45.93,29.89 45.93,28.4 45.59,28.07 R221.2
GPIO3_21: length 30
  TOP w0.121: v1(44.83,22.61) 44.7,22.73 44.7,25.91 45.78,26.98 45.78,27.34 U5.A14
  LYR4 w0.133: v1(44.83,22.61) 44.32,22.1 44.32,21.72 45.21,20.83 45.21,20.32 46.35,19.18 46.35,17.53 47.18,16.7 47.18,12 47.37,11.81 47.37,8.26 50.04,5.59 50.67,5.59 51.18,5.08 51.18,2.92 P9.25
GRN_C: length 2
  BOTTOM w0.121: R128.2 5.21,32.26 4.88,32.59 P10.10
GRNA: length 33.3
  TOP w0.121: v1(25.4,28.96) 25.28,29.07 U15.3
  LYR3 w0.133: P10.9 3.35,30.94 7.62,26.67 9.4,26.67 11.68,24.38 17.53,24.38 19.56,26.42 20.7,26.42 23.75,29.46 24.89,29.46 v1(25.4,28.96)
HS_IND: length 9.3
  TOP w0.121: U11.16 21.95,44.43 22.86,45.34 22.86,47.75 23.28,48.17 24.48,48.17 25.91,46.74 TP8.1
HUB_BIAS: length 3.3
  TOP w0.121: v1(17.14,39.69) 17.14,40.01 17.91,40.77 U11.26
  BOTTOM w0.121: R157.1 16.95,39.05 17.14,39.24 v1(17.14,39.69)
I2C0_SCL: length 37.9
  TOP w0.121: v1(29.72,14.86) 29.07,15.51 U2.28 ; v1(43.93,28.69) U5.C16
  LYR3 w0.133: v1(29.72,14.86) 30.48,14.86 34.42,18.8 40.39,18.8 v1(41.91,20.32)
  BOTTOM w0.121: v1(41.91,20.32) 42.42,19.81 43.19,19.81 43.43,20.06 43.43,21.46 43.18,21.72 43.18,26.92 43.53,27.27 43.53,28.29 v1(43.93,28.69) ; 29.78,9.27 28.45,9.27 28.19,9.53 28.19,11.43 29.32,12.55 29.32,14.46 v1(29.72,14.86) 30.1,15.24 31.5,15.24 31.75,14.99 R7.2
I2C0_SDA: length 32.9
  TOP w0.121: v1(29.72,14.16) 29.34,14.53 29.34,14.67 28.91,15.11 U2.27 ; U5.C17 43.13,28.69 42.15,28.69 41.4,27.94 v1(40.51,27.94)
  LYR3 w0.133: v1(29.72,14.16) 29.31,14.57 29.31,15.09 29.57,15.34 30.58,15.34 34.29,19.05 39.24,19.05 v1(40.51,20.32)
  LYR4 w0.133: v1(40.51,20.32) 40.51,20.83 39.88,21.46 39.88,27.3 v1(40.51,27.94)
  BOTTOM w0.121: R4.2 30.04,14.48 v1(29.72,14.16) 30.12,13.76 30.12,11.64 29.78,11.3 U7.5
I2C1_SCL: length 33.2
  TOP w0.121: U5.A16 v1(43.93,27.09)
  LYR4 w0.133: v1(38.1,17.27) 38.1,18.16 38.23,18.29 38.73,18.29 38.86,18.16 38.86,3.05 P9.17
  BOTTOM w0.121: v1(43.93,27.09) 43.43,26.59 43.43,21.84 43.69,21.59 43.69,19.94 43.31,19.56 40.39,19.56 v1(38.1,17.27)
I2C1_SDA: length 33
  TOP w0.121: U5.B16 v1(43.93,27.89)
  LYR3 w0.133: v1(37.21,27.05) 38.73,28.57 43.24,28.57 v1(43.93,27.89)
  LYR4 w0.133: v1(37.21,27.05) 37.21,27.3 37.34,27.43 37.85,27.43 37.97,27.3 37.97,20.45 39.5,18.92 39.5,6.73 40.01,6.22 P9.18
I2C2_SCL: length 33.8
  TOP w0.121: U5.D17 43.13,29.49 42.06,29.49 41.18,28.6 40.16,28.6 39.5,27.94 39.5,27.56 v1(38.99,27.05)
  LYR4 w0.133: v1(38.99,27.05) 38.48,26.54 38.48,21.72 39.5,20.7 39.5,19.81 40.01,19.3 40.01,10.03 43.56,6.48 43.56,2.92 P9.19
I2C2_SDA: length 33.7
  TOP w0.121: U5.D18 42.08,29.89 41.04,28.85 40.03,28.85 39.12,27.94 v1(38.99,27.94)
  LYR4 w0.133: v1(38.99,27.94) 38.23,27.18 38.23,21.46 39.26,20.43 39.26,19.67 39.75,19.18 39.75,7.24 40.89,6.1 41.15,6.1 41.27,6.22 41.27,7.62 41.4,7.75 41.66,7.75 41.78,7.62 41.78,5.21 P9.20
JTAG_EMU0: length 37
  TOP w0.121: v1(62.29,13.97) 62.17,13.84 R176.2 60.83,13.84 60.38,13.39 60.38,12 59.94,11.56 56.77,11.56 v1(56.26,12.06) ; v1(45.53,28.69) U5.C14
  LYR4 w0.133: v1(47.62,14.61) 48.13,15.11 48.13,19.18 45.47,21.84 45.47,22.86 45.21,23.11 45.21,26.54 45.53,26.86 v1(45.53,28.69)
  BOTTOM w0.121: v1(62.29,13.97) 62.29,14.38 62.52,14.61 P7.13 ; v1(47.62,14.61) 47.62,13.97 49.02,12.57 54.99,12.57 55.12,12.45 R170.2 v1(56.26,12.06)
JTAG_EMU1: length 43
  TOP w0.121: U5.B14 45.53,27.89 45.53,27.11 44.41,26 44.41,22.26 v1(44.83,21.84)
  LYR4 w0.133: v1(44.83,21.84) 45.09,21.84 46.99,19.94 46.99,17.65 47.62,17.02 v1(47.62,16.38)
  BOTTOM w0.121: v1(47.62,16.38) 48.26,15.75 48.26,13.72 49.15,12.83 54.99,12.83 55.12,12.95 R171.2 56.9,13.34 59.44,10.79 R179.2 60.45,11.24 60.64,11.43 66.1,11.43 66.87,12.19 66.87,13.72 67.75,14.61 P7.14
JTAG_TCK: length 40.7
  TOP w0.121: U5.A12 47.53,27.34 46.54,26.35 46.06,26.35 45.5,25.79 45.5,23.58 45.5,21.95 47.26,20.19 47.55,20.19 49.02,20.19 49.21,20.01 49.21,18.02 48.97,17.78 48.39,17.78 47.18,16.57 47.18,11.75 49.18,9.74 49.18,8.85 v1(49.78,8.26)
  LYR3 w0.133: v1(59.63,12.06) 55.31,7.75 50.29,7.75 v1(49.78,8.26)
  BOTTOM w0.121: R164.2 49.66,8.13 v1(49.78,8.26) ; R180.1 R178.1 v1(59.63,12.06)
JTAG_TDI: length 57.4
  TOP w0.121: v1(56.01,6.99) 55.5,6.48 52.32,6.48 49.53,9.27 49.53,9.9 48.13,11.3 48.13,16.89 48.64,17.4 49.08,17.4 49.56,17.87 49.56,17.94 49.56,20.16 49.18,20.54 47.4,20.54 45.85,22.09 45.85,23.72 45.85,24.51 47.08,25.75 47.08,26.39 47.94,27.26 47.94,27.9 U5.B11
  BOTTOM w0.121: 64.29,8.26 66.55,8.26 67.18,7.62 71.25,7.62 71.37,7.49 71.37,6.22 71.12,5.97 57.02,5.97 v1(56.01,6.99) R165.2
JTAG_TDO: length 40.5
  TOP w0.121: v1(52.7,11.43) 53.14,11.86 53.14,16.08 50.04,19.18 50.04,20.19 49.28,20.95 47.5,20.95 46.2,22.25 46.2,24.23 48.24,26.27 48.24,26.97 48.33,27.05 U5.A11
  BOTTOM w0.121: P7.7 63.18,10.79 62.55,10.16 58.17,10.16 56.9,11.43 v1(52.7,11.43) 52.2,10.92 52.2,8.13 52.7,7.62 54.86,7.62 55.12,7.87 R166.2
JTAG_TMS: length 36
  TOP w0.121: v1(47.93,28.69) U5.C11
  LYR4 w0.133: v1(52.7,8.89) 51.82,9.78 51.82,15.49 51.31,16 51.31,18.29 49.05,20.55 49.05,27.57 v1(47.93,28.69)
  BOTTOM w0.121: P7.1 62.61,6.99 61.98,6.35 59.05,6.35 55.88,9.53 R168.2 55.12,9.14 54.86,8.89 v1(52.7,8.89)
JTAG_TRSTN: length 43.3
  TOP w0.121: v1(52.7,10.16) 53.39,10.85 53.39,16.21 50.29,19.3 50.29,20.32 49.4,21.21 47.62,21.21 46.45,22.39 46.45,24.09 48.51,26.16 48.51,26.8 48.73,27.01 48.73,27.89 U5.B10
  BOTTOM w0.121: v1(52.7,10.16) 54.99,10.16 55.12,10.29 R169.2 55.88,10.79 59.05,7.62 61.21,7.62 61.47,7.37 R186.1 62.1,6.99 62.74,7.62 66.55,7.62 67.18,6.99 P7.2
LDO3: length 9.1
  TOP w0.121: v1(20.57,20.32) 21.84,21.59 26.16,21.59 26.54,21.21 26.54,20.73 26.38,20.57 26.38,19.6 U2.40
  BOTTOM w0.121: R19.1 v1(20.57,20.32)
LDO4: length 2.5
  TOP w0.121: v1(25.2,20.95) U2.43
  BOTTOM w0.121: R121.1 25.4,21.15 v1(25.2,20.95)
LDO_PGOOD: length 13.1
  TOP w0.121: U2.46 v1(24,20.32)
  LYR4 w0.133: v1(24,20.32) 24,20.7 23.88,20.83 23.88,23.11 25.02,24.26 29.65,24.26 v1(30.16,24.77)
  BOTTOM w0.121: R141.2 30.77,26.54 30.64,26.42 30.64,24.89 30.51,24.77 v1(30.16,24.77)
LED2: length 28.7
  TOP w0.121: U15.2 24.78,29.1 v1(24.64,28.96)
  LYR3 w0.133: P10.12 4.88,24.43 6.86,26.42 9.27,26.42 11.56,24.13 17.65,24.13 19.68,26.16 20.83,26.16 23.11,28.45 24.13,28.45 v1(24.64,28.96)
  BOTTOM w0.121: R219.1 5.21,25.1 4.88,24.77 P10.12
LEDAA: length 2.5
  TOP w0.121: D2.2 TP10.1 R96.2
LEDAC: length 34.6
  TOP w0.121: v1(33.53,47.75) 33.77,47.51 Q1.6 ; D2.1 2.73,47.75 v1(2.16,47.75)
  BOTTOM w0.121: v1(2.16,47.75) 16.13,47.75 17.4,49.02 32.26,49.02 v1(33.53,47.75)
LEDBA: length 2.5
  TOP w0.121: D3.2 TP11.1 R97.2
LEDBC: length 36.6
  TOP w0.121: Q1.3 32.27,45.2 v1(32.51,44.96) ; D3.1 v1(2.16,46.67)
  BOTTOM w0.121: v1(32.51,44.96) 31.37,44.96 30.86,45.47 30.86,46.1 31.37,46.61 31.37,47.37 29.97,48.77 17.53,48.77 16.26,47.5 2.98,47.5 v1(2.16,46.67)
LEDCA: length 2.5
  TOP w0.121: D4.2 TP12.1 R98.2
LEDCC: length 31.2
  TOP w0.121: Q2.6 29.96,47.51 v1(29.72,47.75) ; D4.1 v1(2.16,45.09)
  BOTTOM w0.121: v1(2.16,45.09) 4.32,47.24 16.38,47.24 17.65,48.51 28.96,48.51 v1(29.72,47.75)
LEDDA: length 2.5
  TOP w0.121: R99.2 TP13.1 D5.2
LEDDC: length 33.3
  TOP w0.121: D5.1 v1(2.16,43.5) ; Q2.3 28.46,45.2 v1(28.7,44.96)
  BOTTOM w0.121: v1(2.16,43.5) 5.65,46.99 16.51,46.99 17.78,48.26 26.8,48.26 27.16,47.9 27.16,45.36 27.56,44.96 v1(28.7,44.96)
MDIO_CLK: length 16.8
  TOP w0.121: v1(36.45,36.83) 36.96,37.34 39.24,37.34 39.62,36.96 41.27,36.96 42.04,36.2 42.63,36.2 U5.M18 ; v1(28.45,35.81) 27.79,35.15 U15.17
  BOTTOM w0.121: v1(36.45,36.83) 36.2,37.08 32.64,37.08 32.13,36.58 29.21,36.58 v1(28.45,35.81)
MDIO_DATA: length 20.1
  TOP w0.121: v1(37.21,36.83) 37.72,36.32 38.48,36.32 38.86,36.7 41.02,36.7 41.83,35.89 43.13,35.89 U5.M17 ; U15.16 28.8,34.14 28.96,34.29 28.96,35.43 v1(29.34,35.81)
  BOTTOM w0.121: v1(37.21,36.83) 36.7,36.32 36.07,36.32 35.56,36.83 32.89,36.83 32.38,36.32 29.84,36.32 v1(29.34,35.81) 28.13,34.61 R131.2
MMC0_CLKO: length 73.4
  TOP w0.121: R192.2 v1(80.52,34.54) ; U5.G17 43.13,32.69 42.34,32.69 41.4,31.75 40.39,31.75 39.62,30.99 38.86,30.99 36.45,28.57 36.45,22.99 v1(37.21,22.23)
  LYR3 w0.133: v1(37.21,22.23) 37.87,21.57 39.35,21.57 41.53,23.75 56.01,23.75 57.4,22.35 71.25,22.35 74.3,25.4 78.11,25.4 81.53,28.83 81.53,33.53 v1(80.52,34.54)
  BOTTOM w0.121: v1(80.52,34.54) R192.2 81.6,34.22 P4.5
MMC0_CMD: length 72.5
  TOP w0.121: v1(37.21,22.99) 36.7,23.5 36.7,28.07 38.35,29.72 39.02,29.72 40.04,30.73 40.77,30.73 42.32,32.29 U5.G18 ; R191.2 v1(80.52,31.75)
  LYR3 w0.133: v1(37.21,22.99) 38.38,21.82 39.22,21.82 41.4,24 59.69,24 59.82,23.88 59.82,23.5 59.69,23.37 57.78,23.37 57.66,23.24 57.66,22.73 57.78,22.61 71.12,22.61 74.17,25.65 77.85,25.65 81.28,29.08 81.28,30.99 v1(80.52,31.75)
  BOTTOM w0.121: P4.3 81.55,32.02 R191.2 v1(80.52,31.75)
MMC0_DAT0: length 72.5
  TOP w0.121: v1(43.93,31.89) U5.G16 ; R193.2 v1(80.52,36.58)
  LYR3 w0.133: v1(80.52,36.58) 80.9,36.58 82.04,35.43 82.04,28.32 78.61,24.89 74.55,24.89 71.5,21.84 56.9,21.84 56.37,22.37 47.87,22.37 47.75,22.48 47.75,22.65 47.87,22.76 50.31,22.76 50.42,22.87 50.42,23.02 50.31,23.13 44.45,23.13 43.9,22.58 41.81,22.58 41.4,22.99 v1(41.4,22.99)
  LYR4 w0.133: v1(43.93,31.89) 43.73,31.89 43.22,31.38 42.55,30.71 42.55,27.62 42.74,27.43 42.74,24.32 v1(41.4,22.99)
  BOTTOM w0.121: v1(80.52,36.58) 82.36,36.58 P4.7
MMC0_DAT1: length 72.2
  TOP w0.121: R194.2 v1(80.52,37.59) ; v1(44.73,31.89) U5.G15
  LYR3 w0.133: v1(80.52,37.59) 80.01,37.08 80.01,36.32 80.26,36.07 80.9,36.07 81.79,35.18 81.79,28.57 78.36,25.15 74.42,25.15 71.37,22.1 57.15,22.1 56.64,22.61 52.44,22.61 52.32,22.72 52.32,22.88 52.44,22.99 54.48,22.99 54.61,23.11 54.61,23.37 54.48,23.5 44.2,23.5 43.69,22.99 v1(42.04,22.99)
  LYR4 w0.121: v1(44.73,31.89) 44.33,31.49 43.76,31.49 43.55,31.27
  LYR4 w0.133: 43.55,31.27 42.8,30.52 42.8,27.86 42.97,27.69 42.97,23.92 v1(42.04,22.99)
  BOTTOM w0.121: P4.8 82.44,37.59 v1(80.52,37.59)
MMC0_DAT2: length 72.3
  TOP w0.121: U5.F18 41.89,31.49 40.88,30.48 40.13,30.48 39.12,29.46 38.73,29.46 37.72,28.45 37.72,23.5 v1(38.99,22.23) ; R190.2 v1(80.52,29.72)
  LYR3 w0.133: v1(38.99,22.23) 38.48,22.73 38.48,23.24 39.75,24.51 52.7,24.51 54.23,26.04 61.59,26.04 61.72,25.91 61.72,25.65 61.59,25.53 58.55,25.53 58.42,25.4 58.42,25.15 58.55,25.02 61.59,25.02 61.72,24.89 61.72,23.24 61.85,23.11 70.87,23.11 73.91,26.16 77.34,26.16 80.52,29.34 v1(80.52,29.72)
  BOTTOM w0.121: v1(80.52,29.72) 82.41,29.72 P4.1
MMC0_DAT3: length 72.4
  TOP w0.121: v1(38.99,22.99) 37.97,24 37.97,28.32 38.86,29.21 39.24,29.21 40.25,30.22 41.01,30.22 41.88,31.09 43.13,31.09 U5.F17 ; R195.2 v1(80.52,30.73)
  LYR3 w0.133: v1(38.99,22.99) 40.26,24.26 52.96,24.26 54.23,25.53 57.78,25.53 57.91,25.4 57.91,25.15 57.78,25.02 54.36,25.02 54.23,24.89 54.23,24.64 54.36,24.51 61.09,24.51 61.21,24.38 61.21,22.99 61.34,22.86 70.99,22.86 74.04,25.91 77.6,25.91 81.03,29.34 81.03,30.23 v1(80.52,30.73)
  BOTTOM w0.121: P4.2 82.33,30.73 v1(80.52,30.73)
Net_69: length 0.6
  TOP w0.121: v1(46.33,39.89) 46.73,39.49
Net_134: length 0.6
  TOP w0.121: 69.53,36.69 v1(69.13,37.09)
Net_135: length 0.6
  TOP w0.121: 69.53,39.89 v1(69.13,40.29)
Net_136: length 0.6
  TOP w0.121: 70.33,28.69 v1(69.93,28.29)
Net_137: length 0.6
  TOP w0.121: 73.53,28.69 v1(73.93,28.29)
Net_271: length 0.6
  TOP w0.121: v1(54.33,32.69) 53.93,33.09
Net_274: length 0.6
  TOP w0.121: v1(45.53,39.09) 45.93,38.69
NINT/RXCLK/PHYAD1: length 3
  BOTTOM w0.121: 21.46,27.62 21.46,28.57 22.16,28.57 v1(23.11,29.53)
NON_REM1: length 3.6
  TOP w0.121: 25.53,41.91 24.38,41.91 24,42.29 23.37,42.29 U11.13 ; 25.53,41.91 R158.1 ; 25.53,41.91 R154.2
NON_REM2: length 6.3
  TOP w0.121: TP7.1 19.68,45.85 20.45,45.08 U11.19
OSC0_IN: length 13.3
  TOP w0.121: 44.45,45.85 43.18,45.85 43.18,45.09 v1(43.69,44.58) 43.95,44.32 46.6,44.32 49.13,41.79 U5.V10
  BOTTOM w0.121: Y2.3 45.3,45.55 Y3.3 43.69,45.51 v1(43.69,44.58)
OSC0_OUT: length 10.6
  TOP w0.121: 41.91,45.85 41.91,45.21 43.05,44.07 46.5,44.07 48.73,41.84 48.73,40.69 U5.U11
OSC0_OUT1: length 7.3
  TOP w0.121: R21.2 R24.1 ; R24.1 C27.1 ; R24.1 41.91,47.62 v1(41.4,48.13)
  BOTTOM w0.121: Y2.1 39.79,47.16 Y3.1 41.4,47.2 v1(41.4,48.13)
OSC1_IN: length 11
  TOP w0.121: Y1.1 55.24,19.59 v1(55.24,20.32) 54.99,20.57 54.36,20.57 52.96,21.97 52.96,25.53 52.67,25.82 52.67,27.15 U5.A6
  BOTTOM w0.121: C23.2 v1(55.24,20.32)
OSC1_OUT: length 4
  TOP w0.121: R22.2 53.85,23.81 53.85,24.6 53.82,24.63 53.82,25.54 54.08,25.8 54.08,26.94 53.93,27.1 U5.A4
OSC1_OUT1: length 7.3
  TOP w0.121: R22.1 53.98,22.23 54.86,21.34 56.2,21.34 56.96,20.57 57.53,20.57 v1(57.78,20.32) 57.78,19.59 Y1.2
  BOTTOM w0.121: C24.2 v1(57.78,20.32)
P_BYPASS: length 3.4
  TOP w0.121: v1(22.73,20.32) 23.37,20.32 23.6,20.09 U2.47
  BOTTOM w0.121: v1(22.73,20.32) 22.73,21.27 C5.2
P_INT_LDO: length 4.4
  TOP w0.121: U2.48 22.71,19.58 22.1,20.19 v1(22.1,20.83)
  BOTTOM w0.121: v1(22.1,20.83) 21.34,20.83 20.19,21.97 C4.2
P_L1: length 1
  TOP w0.203: U2.20 26,12.45
P_L2: length 0.6
  TOP w0.203: 27.2,12.8 U2.23
P_L3: length 1.1
  TOP w0.203: U2.31 29.01,16.71 ; 29.01,16.71 29.26,16.71 ; 29.01,16.71 29.21,16.51
P_MUXIN: length 6.6
  TOP w0.121: v1(23.11,12.45) 23.22,12.45 23.6,12.83 U2.14
  BOTTOM w0.121: R2.1 R1.2 22.48,9.4 22.35,9.53 22.35,11.68 v1(23.11,12.45)
P_MUXOUT: length 12.6
  TOP w0.121: v1(23.88,12.45) 24,12.45 24.4,12.84 U2.16
  LYR4 w0.133: v1(23.88,12.45) 27.69,16.26 v1(27.69,20.95)
  BOTTOM w0.121: v1(27.69,20.95) 27.3,21.34 R8.2
P_WAKEUP: length 3.4
  TOP w0.121: v1(22.35,12.45) 22.35,12.95 22.83,13.44 U2.13
  BOTTOM w0.121: v1(22.35,12.45) 22.83,12.92 23.27,12.92 R11.1
PDDR_A0: length 7.1
  TOP w0.121: U5.F3 v1(55.13,31.09)
  BOTTOM w0.121: v1(55.13,31.09) 55.28,31.24 56.52,31.24 56.75,31.01 56.75,28.83 56.88,28.7 57.57,28.7 57.89,28.38 58.55,28.38 58.67,28.51 58.67,28.77 R29.2
PDDR_A1: length 6.5
  TOP w0.121: R25.2 59.44,31.75 59.04,32.15 58.83,32.15 57.97,32.15 57.66,32.46 57.66,32.56 57.73,32.64 58.6,32.64 58.67,32.71 58.67,32.82 58.6,32.89 57.35,32.89 57.15,33.09 U5.H1
PDDR_A2: length 8
  TOP w0.121: U5.E4 v1(54.33,30.29)
  BOTTOM w0.121: R30.2 57.91,26.04 57.47,26.48 57.47,27.5 57.09,27.88 56.2,27.88 56.01,28.07 56.01,29.46 55.63,29.84 54.78,29.84 v1(54.33,30.29)
PDDR_A3: length 7.2
  TOP w0.121: v1(55.13,28.69) U5.C3
  BOTTOM w0.121: R26.2 56.83,27.1 56.73,27.2 55.6,27.2 55.5,27.3 55.5,27.71 55.4,27.81 55.22,27.81 55.12,27.71 55.12,27.3 55.02,27.2 54.84,27.2 54.74,27.3 54.74,28.09 54.84,28.19 55.03,28.19 55.13,28.3 v1(55.13,28.69)
PDDR_A4: length 7.2
  TOP w0.121: U5.C2 55.93,28.69 56.65,28.69 58.18,27.16 58.18,24.68 58.74,24.13 R31.2
PDDR_A5: length 7.1
  TOP w0.121: U5.B1 56.7,28.29 57.14,27.85 57.14,27.3 57.27,27.18 57.78,27.18 57.91,27.05 57.91,26.8 57.78,26.67 57.26,26.67 57.15,26.56 57.15,26.4 57.26,26.28 57.78,26.28 57.94,26.13 57.94,24.38 57.78,24.23 R32.2
PDDR_A6: length 6.6
  TOP w0.121: v1(53.53,29.49) U5.D5
  BOTTOM w0.121: R33.2 54.99,25.34 54.99,26.43 54.88,26.54 54.72,26.54 54.61,26.43 54.61,26.15 54.5,26.04 54.34,26.04 54.23,26.15 54.23,28.13 53.93,28.43 53.93,28.65 53.93,29.09 v1(53.53,29.49)
PDDR_A7: length 7.4
  TOP w0.121: U5.E2 55.93,30.29 56.58,30.29 59.19,27.68 59.19,26.28 59.44,26.04 R34.2
PDDR_A8: length 8.2
  TOP w0.121: v1(54.33,29.49) U5.D4
  BOTTOM w0.121: R35.2 58.1,25.08 57.15,26.04 57.15,27.43 57.02,27.56 56.01,27.56 55.75,27.81 55.75,29.08 55.35,29.49 v1(54.33,29.49)
PDDR_A9: length 8
  TOP w0.121: U5.C1 56.63,29.09 58.43,27.29 58.43,27.06 58.43,27.06 58.43,25.01 59.37,24.07 59.37,23.37 59.56,23.18 R36.2
PDDR_A10: length 7.1
  TOP w0.121: U5.F4 v1(54.33,31.09)
  BOTTOM w0.121: R37.2 58.42,27.81 57.91,27.81 57.35,28.37 56.72,28.37 56.5,28.59 56.5,28.86 56.5,30.11 55.92,30.69 54.73,30.69 v1(54.33,31.09)
PDDR_A11: length 6.4
  TOP w0.121: U5.F2 55.93,31.09 57.15,31.09 57.27,30.97 57.27,30.36 59.69,27.94 R38.2
PDDR_A12: length 7.3
  TOP w0.121: v1(55.13,30.29) U5.E3
  BOTTOM w0.121: R39.2 58.55,26.64 58.45,26.54 57.91,26.54 57.78,26.67 57.78,27.56 57.22,28.12 56.45,28.12 56.25,28.32 56.25,28.96 56.25,29.72 55.69,30.29 v1(55.13,30.29)
PDDR_A13: length 7.8
  TOP w0.121: U5.H3 v1(55.13,32.69)
  BOTTOM w0.121: R40.2 57.66,31.75 57.4,32 55.61,32 55.5,32.12 55.5,32.27 55.61,32.38 56.9,32.38 57.02,32.51 57.02,32.72 56.9,32.84 55.28,32.84 v1(55.13,32.69)
PDDR_BA0: length 7
  TOP w0.121: U5.C4 v1(54.33,28.69)
  BOTTOM w0.121: v1(54.33,28.69) 54.48,28.54 54.48,27.05 54.6,26.92 55.12,26.92 55.24,26.8 55.24,25.88 55.35,25.78 55.5,25.78 55.6,25.88 55.6,26.57 55.7,26.67 55.89,26.67 56.01,26.55 56.01,25.4 R41.2
PDDR_BA1: length 7.3
  TOP w0.121: R42.2 60.33,26.8 60.33,26.62 60.25,26.54 59.56,26.54 59.44,26.67 59.44,27.81 57.02,30.23 57.02,30.26 57.02,30.26 57.02,30.73 56.91,30.84 56.48,30.84 U5.E1
PDDR_BA2: length 6.8
  TOP w0.121: U5.B3 55.13,27.89 55.13,27.32 54.86,27.05 54.86,26.9 54.97,26.8 55.39,26.8 55.5,26.69 55.5,26.53 55.39,26.42 54.98,26.42 54.86,26.3 54.86,26.16 54.99,26.04 55.75,26.04 55.88,25.91 R43.2
PDDR_CASN: length 6.7
  TOP w0.121: R64.2 60.33,28.7 60.33,28.52 60.25,28.45 59.53,28.45 59.04,28.94 59.04,29.86 58.96,29.94 58.04,29.94 57.52,30.46 57.52,31.13 57.16,31.49 U5.F1
PDDR_CKE: length 7.8
  TOP w0.121: U5.G3 v1(55.13,31.89)
  BOTTOM w0.121: R62.2 57.79,30.8 57.66,30.67 57.66,29.33 57.55,29.21 57.39,29.21 57.27,29.33 57.27,31.5 57.02,31.75 55.27,31.75 v1(55.13,31.89)
PDDR_CLK: length 8.3
  TOP w0.095: R60.2 59.95,24.31 59.63,24.31 58.67,25.27 58.67,27.43 56.62,29.49 55.93,29.49 U5.D2
PDDR_CLKN: length 8.2
  TOP w0.095: U5.D1 56.61,29.89 58.95,27.55 58.95,25.39 59.75,24.59 60.38,24.59 60.45,24.67 60.45,24.77 R61.2
PDDR_CSN: length 6.9
  TOP w0.121: R63.2 60.33,30.61 60.33,30.43 60.25,30.35 59.69,30.35 59.56,30.48 59.56,31.27 58.94,31.9 57.87,31.9 57.08,32.69 55.93,32.69 U5.H2
PDDR_D0: length 6.4
  TOP w0.121: v1(55.13,36.69) U5.M3
  BOTTOM w0.121: R44.2 58.67,36.64 58.67,36.9 58.55,37.02 57.79,37.02 57.66,37.15 57.66,38.09 57.4,38.35 57.12,38.35 55.46,36.69 v1(55.13,36.69)
PDDR_D1: length 7.5
  TOP w0.121: v1(54.33,36.69) U5.M4
  BOTTOM w0.121: v1(54.33,36.69) 54.73,37.09 55.51,37.09 57.14,38.73 57.14,39.12 57.27,39.24 57.43,39.24 57.66,39.01 57.66,38.44 57.91,38.19 57.91,37.59 58.04,37.47 R45.2
PDDR_D2: length 6.7
  TOP w0.121: U5.N1 57.54,37.09 57.78,37.34 57.78,38.1 58.29,38.61 58.93,38.61 59.18,38.86 59.18,40.39 59.44,40.64 59.82,40.64 R46.2
PDDR_D3: length 7.4
  TOP w0.121: U5.N2 55.93,37.49 56.77,37.49 58.13,38.86 58.67,38.86 58.93,39.12 58.93,40.89 59.31,41.27 R47.2
PDDR_D4: length 7.8
  TOP w0.121: U5.N3 v1(55.13,37.49)
  BOTTOM w0.121: v1(55.13,37.49) 55.52,37.49 56.9,38.86 56.9,40.39 57.02,40.51 57.28,40.51 57.4,40.39 57.4,39.62 57.91,39.12 57.91,38.54 58.04,38.42 R48.2
PDDR_D5: length 8.2
  TOP w0.121: U5.N4 v1(54.33,37.49)
  BOTTOM w0.121: v1(54.33,37.49) 54.73,37.89 55.54,37.89 56.64,38.99 56.64,40.64 56.77,40.77 57.53,40.77 57.66,40.64 57.66,39.75 58.04,39.37 R49.2
PDDR_D6: length 6.6
  TOP w0.121: U5.P3 v1(55.13,38.29)
  BOTTOM w0.121: R50.2 58.04,40.32 57.91,40.45 57.91,40.89 57.78,41.02 56.61,41.02 56.39,40.8 56.39,39.12 55.56,38.29 v1(55.13,38.29)
PDDR_D7: length 7
  TOP w0.121: U5.P4 v1(54.33,38.29)
  BOTTOM w0.121: R51.2 56.52,41.27 56.13,40.89 56.13,39.24 55.58,38.69 54.73,38.69 v1(54.33,38.29)
PDDR_D8: length 6.9
  TOP w0.121: R52.2 60.33,33.46 60.33,33.25 60.25,33.18 59.73,33.18 59.6,33.05 59.6,32.59 59.52,32.51 59.38,32.51 59.18,32.71 59.18,33.32 59.11,33.39 57.73,33.39 57.66,33.47 57.66,34.09 57.58,34.16 57.35,34.16 57.28,34.09 57.28,33.81 57.2,33.74 56.48,33.74 U5.J1
PDDR_D9: length 6.6
  TOP w0.121: R53.2 60.33,34.42 60.33,34.21 60.25,34.13 59.64,34.13 59.56,34.05 59.56,33.73 59.49,33.66 57.98,33.66 57.91,33.73 57.91,34.72 57.83,34.8 57.61,34.8 57.53,34.72 57.53,34.49 57.45,34.42 57.23,34.42 57.15,34.49 57.15,34.72 57.07,34.8 56.44,34.8 U5.K1
PDDR_D10: length 7.3
  TOP w0.121: R54.2 59.64,35.56 59.56,35.48 59.56,34.4 59.32,34.16 59.32,33.99 59.24,33.91 58.24,33.91 58.17,33.99 58.17,35.01 58.09,35.09 55.93,35.09 U5.K2
PDDR_D11: length 7.2
  TOP w0.121: v1(55.13,35.09) U5.K3
  BOTTOM w0.121: v1(55.13,35.09) 55.41,35.09 56.52,36.2 56.86,36.2 57.28,35.78 57.28,33.53 58.1,32.7 R55.2
PDDR_D12: length 7.8
  TOP w0.121: U5.K4 v1(54.33,35.09)
  BOTTOM w0.121: R56.2 57.79,33.66 57.54,33.91 57.54,35.87 56.83,36.58 56.53,36.58 55.45,35.49 54.73,35.49 v1(54.33,35.09)
PDDR_D13: length 7.6
  TOP w0.121: v1(55.13,35.89) U5.L3
  BOTTOM w0.121: R57.2 58.67,34.48 58.67,34.29 58.55,34.16 57.91,34.16 57.78,34.29 57.78,35.97 57.12,36.63 57.12,37.08 57,37.21 56.77,37.21 55.45,35.89 v1(55.13,35.89)
PDDR_D14: length 7.5
  TOP w0.121: U5.L4 v1(54.33,35.89)
  BOTTOM w0.121: v1(54.33,35.89) 54.73,36.29 55.41,36.29 56.96,37.85 57.25,37.85 57.37,37.72 57.37,36.73 58.04,36.07 58.55,36.07 58.67,35.94 58.67,35.69 R58.2
PDDR_D15: length 7.2
  TOP w0.121: U5.M1 56.57,36.29 57.02,35.83 57.28,35.83 57.4,35.96 57.4,36.22 57.51,36.32 57.81,36.32 57.91,36.22 57.91,35.92 58,35.83 58.34,35.83 58.42,35.92 58.42,37.84 58.52,37.94 60.06,37.94 60.13,38.02 R59.2
PDDR_DQM0: length 7
  TOP w0.121: U5.M2 55.93,36.69 57.78,36.69 58.03,36.94 58.03,37.97 58.42,38.35 59.18,38.35 59.44,38.61 59.44,39.37 59.56,39.5 60.01,39.5 R67.2
PDDR_DQM1: length 6.4
  TOP w0.121: R70.2 60.33,32.51 60.33,32.3 60.25,32.23 59.31,32.23 58.93,32.61 58.93,33.07 58.85,33.15 57.48,33.15 57.4,33.22 57.4,33.41 57.33,33.49 55.93,33.49 U5.J2
PDDR_DQS0: length 7.1
  TOP w0.121: U5.P1 56.78,37.89 58,39.1 58.41,39.1 58.67,39.37 58.67,41.94 58.96,42.23 R68.2
PDDR_DQS1: length 7
  TOP w0.121: U5.L1 56.48,35.34 58.29,35.34 58.41,35.21 58.41,35.12 58.41,34.91 58.41,34.91 58.41,34.24 58.49,34.16 58.97,34.16 59.31,34.5 59.31,36.44 59.39,36.51 R71.2
PDDR_DQSN0: length 8.1
  TOP w0.121: U5.P2 55.93,38.29 56.83,38.29 58.42,39.88 58.42,42.04 59.56,43.18 R69.2
PDDR_DQSN1: length 7.7
  TOP w0.121: U5.L2 55.93,35.89 56.52,35.89 56.82,35.58 58.7,35.58 58.8,35.69 58.8,37.36 58.9,37.47 59.08,37.47 59.18,37.36 59.18,36.93 59.28,36.83 59.44,36.83 59.56,36.96 59.56,37.34 59.69,37.47 R72.2
PDDR_ODT: length 6.7
  TOP w0.121: U5.G1 57.13,32.29 57.77,31.65 58.83,31.65 59.31,31.18 59.31,29.5 59.44,29.37 60.25,29.37 60.33,29.44 60.33,29.65 R73.2
PDDR_RASN: length 8
  TOP w0.121: U5.G4 v1(54.33,31.89)
  BOTTOM w0.121: v1(54.33,31.89) 54.73,31.49 56.77,31.49 57.02,31.24 57.02,29.08 57.15,28.96 57.78,28.96 57.91,29.08 57.91,29.72 58.04,29.84 R65.2
PDDR_WEN: length 6.6
  TOP w0.121: U5.B2 55.93,27.89 56.64,27.89 56.9,27.64 56.9,26.16 57.02,26.04 57.56,26.04 57.69,25.91 57.69,24.67 56.83,23.81 R66.2
